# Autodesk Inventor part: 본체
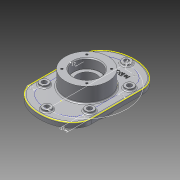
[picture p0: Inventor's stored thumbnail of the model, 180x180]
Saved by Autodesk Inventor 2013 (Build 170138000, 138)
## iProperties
Created: 2015-02
Part Number: 본체
Material: 알루미늄 6061
Document SubType Name: Modeling
Designer: Administrator
Density: 2.71 g/cm^3
Mass: 1660.48 g
Surface Area: 940.405 cm^2
Volume: 612.722 cm^3
Author: Administrator
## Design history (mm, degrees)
sketch "스케치1" dims "d8" = 70, "d10" = 50, "d11" = 50
  geometry: L1 (70, 60)-(70, -60); L2 (-70, -60)-(-70, 60); 3 further points; 2 other entities
  constraints: 4 end point, 2 vertical alignment, 1 parallel, 8 other
  dimensions: "d5" = 140 distance between parallel lines of L1 L2; "d7" = 120 distance of point (0, 60) point (0, -60)
extrude "돌출1" new body sketch "스케치1" distance "d12" = 12; taper "d13" = 0 deg
sketch "스케치2"
  geometry: C1 r 50 at (0, 0); 1 further point
  constraints: 1 centre point, 1 coincident
  dimensions: "d14" = 100 diameter of C1
extrude "돌출2" join sketch "스케치2" distance "d15" = 35; taper "d16" = 0 deg
sketch "스케치3"
  geometry: C1 r 50 at (0, 0); 1 further point
  constraints: 1 centre point, 1 coincident
  dimensions: "d17" = 100 diameter of C1
extrude "돌출3" join sketch "스케치3" distance "d18" = 23; taper "d19" = 0 deg
sketch "스케치4"
  geometry: L1 (-70, 60)-(-70, -60) reference; L2 (70, -60)-(70, 60) reference; L3 (-53, 60)-(-53, -60); L4 (53, -60)-(53, 60); C1 r 50 at (0, 0) reference; C2 r 10 at (0, 93); C3 r 10 at (-53, 46.5); C4 r 10 at (-53, -46.5); C5 r 10 at (0, -93); C6 r 10 at (53, -46.5); C7 r 10 at (53, 46.5); 2 further points; 2 other entities
  constraints: 6 centre point, 4 end point, 3 parallel, 1 horizontal alignment, 1 vertical alignment, 9 other
  dimensions: "d20" = 17 distance between parallel lines of L2 L4; "d21" = 20 diameter of C2; "d24" = 360 deg dimension on C1.centre C2.centre (derived); "d26" = 17 distance from line of L2 C7.centre; "d27" = 17 distance from line of L2 C6.centre; "d28" = 17 distance from line of L1 C4.centre; "d29" = 17 distance from line of L1 C3.centre
extrude "돌출4" join sketch "스케치4" distance "d30" = 5; taper "d31" = 0 deg
hole "구멍1" diameter "d34" = 11; stored, may be unused: countersink angle "d38" = 90 deg, drill point angle "d40" = 0 deg; dims "d32" = 10, "d33" = 10, "d35" = 6, "d36" = 4, "d37" = 2, "d39" = 8
hole "구멍2" diameter "d43" = 11; stored, may be unused: countersink angle "d47" = 90 deg, drill point angle "d49" = 0 deg; dims "d41" = 10, "d42" = 10, "d44" = 6, "d45" = 4, "d46" = 2, "d48" = 8
hole "구멍3" diameter "d52" = 11; stored, may be unused: countersink angle "d56" = 90 deg, drill point angle "d58" = 0 deg; dims "d50" = 10, "d51" = 10, "d53" = 6, "d54" = 4, "d55" = 2, "d57" = 8
hole "구멍4" diameter "d61" = 11; stored, may be unused: countersink angle "d65" = 90 deg, drill point angle "d67" = 0 deg; dims "d59" = 10, "d60" = 10, "d62" = 6, "d63" = 4, "d64" = 2, "d66" = 8
hole "구멍5" diameter "d70" = 11; stored, may be unused: countersink angle "d74" = 90 deg, drill point angle "d76" = 0 deg; dims "d68" = 10, "d69" = 10, "d71" = 6, "d72" = 4, "d73" = 2, "d75" = 8
hole "구멍6" diameter "d79" = 11; stored, may be unused: countersink angle "d83" = 90 deg, drill point angle "d85" = 0 deg; dims "d77" = 10, "d78" = 10, "d80" = 6, "d81" = 4, "d82" = 2, "d84" = 8
sketch "스케치5"
  geometry: C1 r 50 at (0, 0) reference; C2 r 5.5 at (0, 93) reference; 1 further point
  dimensions: "d86" = 41 distance of point (28.991, 28.991) C1.centre; "d87" = 45 deg dimension on C1.centre point (28.991, 28.991) C2.centre
hole "구멍7" sketch "스케치5" at (28.991, 28.991) diameter "d88" = 4.917; stored, may be unused: countersink angle "d92" = 90 deg, drill point angle "d94" = 118 deg; dims "d89" = 10, "d90" = 4, "d91" = 2, "d93" = 13
sketch "스케치6"
  geometry: C1 r 50 at (0, 0) reference; C2 r 5.5 at (0, 93) reference; 1 further point
  dimensions: "d98" = 41 distance of point (28.991, 28.991) C1.centre; "d99" = 45 deg dimension on C1.centre point (28.991, 28.991) C2.centre
hole "구멍8" sketch "스케치6" at (28.991, 28.991) diameter "d100" = 4.917; stored, may be unused: countersink angle "d104" = 90 deg, drill point angle "d106" = 118 deg; dims "d101" = 10, "d102" = 4, "d103" = 2, "d105" = 13
sketch "스케치7"
  geometry: C1 r 50 at (0, 0) reference
hole "구멍9" sketch "스케치7" at (0, 0) diameter "d110" = 62; stored, may be unused: countersink angle "d114" = 90 deg, drill point angle "d116" = 0 deg; dims "d111" = 10, "d112" = 4, "d113" = 2, "d115" = 22
sketch "스케치8"
  geometry: C1 r 50 at (0, 0) reference
hole "구멍10" sketch "스케치8" at (0, 0) diameter "d117" = 45; stored, may be unused: countersink angle "d121" = 90 deg, drill point angle "d123" = 0 deg; dims "d118" = 10, "d119" = 62, "d120" = 22, "d122" = 22
sketch "스케치9"
  geometry: C1 r 50 at (0, 0) reference; 1 further point
  constraints: 1 vertical alignment, 1 other
  dimensions: "d124" = 65 distance of C1.centre point (0, 65)
feature "엠보싱1" sketch "스케치9" dims "d5" = 140, "d7" = 120, "d8" = 70, "d10" = 50, "d11" = 50, "d125" = 1, "d126" = 0
fillet "모깎기1" dims "d127" = 3
fillet "모깎기2" dims "d128" = 3
fillet "모깎기3" dims "d129" = 0.3
chamfer "모따기1" distance "d130" = 2; stored, may be unused: second distance "d131" = 2, angle "d132" = 45 deg
node "솔리드1"
pattern_circular "원형 패턴1" dims angle "d96" = 360 deg
pattern_circular "원형 패턴2" dims angle "d108" = 360 deg
